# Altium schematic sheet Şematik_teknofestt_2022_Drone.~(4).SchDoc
size A4; SheetNumber: 1; SheetTotal: 1
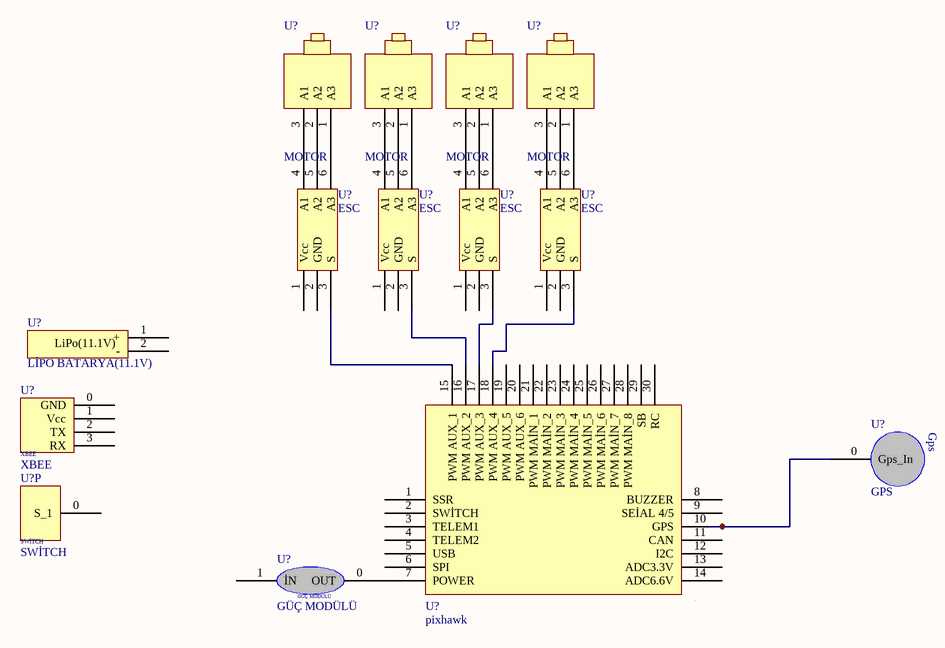
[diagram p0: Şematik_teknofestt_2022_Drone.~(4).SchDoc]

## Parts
(Parts that share a designator on the sheet are numbered #1, #2 ... from top to bottom, then left to right.)
U?#1  pixhawk
U?#2  MOTOR
U?#3  MOTOR
U?#4  MOTOR
U?#5  MOTOR
U?#6  ESC
U?#7  ESC
U?#8  ESC
U?#9  ESC
U?#10  LİPO BATARYA(11.1V)
U?#11  GPS
U?#12  XBEE
U?#13  GÜÇ MODÜLÜ
U?P  SWİTCH

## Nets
NetU?#1_7: U?#1.7(POWER) U?#13.0(OUT)
NetU?#1_10: U?#1.10(GPS) U?#11.0(Gps_In)
NetU?#1_15: U?#1.15(PWM_AUX_1) U?#6.3(S)
NetU?#1_16: U?#1.16(PWM_AUX_2) U?#7.3(S)
NetU?#1_17: U?#1.17(PWM_AUX_3) U?#8.3(S)
NetU?#1_18: U?#1.18(PWM_AUX_4) U?#9.3(S)
NetU?#2_1: U?#2.1(A3) U?#6.6(A3)
NetU?#2_2: U?#2.2(A2) U?#6.5(A2)
NetU?#2_3: U?#2.3(A1) U?#6.4(A1)
NetU?#3_1: U?#3.1(A3) U?#7.6(A3)
NetU?#3_2: U?#3.2(A2) U?#7.5(A2)
NetU?#3_3: U?#3.3(A1) U?#7.4(A1)
NetU?#4_1: U?#4.1(A3) U?#8.6(A3)
NetU?#4_2: U?#4.2(A2) U?#8.5(A2)
NetU?#4_3: U?#4.3(A1) U?#8.4(A1)
NetU?#5_1: U?#5.1(A3) U?#9.6(A3)
NetU?#5_2: U?#5.2(A2) U?#9.5(A2)
NetU?#5_3: U?#5.3(A1) U?#9.4(A1)

Not connected (* = marked no-connect by the designer): U?#1 1(SSR) 2(SWİTCH) 3(TELEM1) 4(TELEM2) 5(USB) 6(SPI) 8(BUZZER) 9(SEİAL_4/5) 11(CAN) 12(I2C) 13(ADC3.3V) 14(ADC6.6V) 19(PWM_AUX_5) 20(PWM_AUX_6) 21(PWM_MAİN_1) 22(PWM_MAİN_2) 23(PWM_MAİN_3) 24(PWM_MAİN_4) 25(PWM_MAİN_5) 26(PWM_MAİN_6) 27(PWM_MAİN_7) 28(PWM_MAİN_8) 29(SB) 30(RC); U?#6 1(Vcc) 2(GND); U?#7 1(Vcc) 2(GND); U?#8 1(Vcc) 2(GND); U?#9 1(Vcc) 2(GND); U?#10 1(+) 2(-); U?#12 0(GND) 1(Vcc) 2(TX) 3(RX); U?#13 1(İN); U?P 0(S_1)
